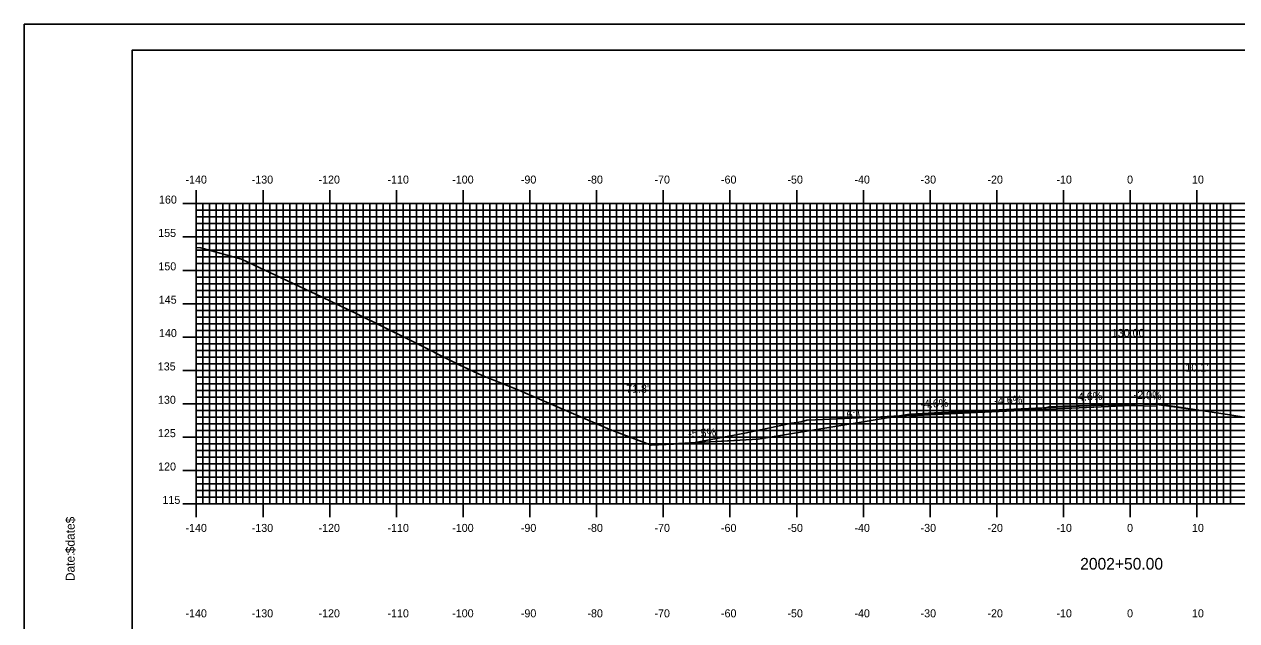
# Model space of a CAD drawing. Extents: x 851139 to 851482, y 366605 to 366825.
# Drawn here: x 851139.2 to 851320.9, y 366735.5 to 366824.9 of the extents above; entities that cross this region are included whole.
import ezdxf

# ---------------------------------------------------------------- set-up
doc = ezdxf.new("R2010")
doc.units = 0
for name, color, linetype in [('ANNOTATION', 7, 'Continuous'), ('BORDER', 7, 'Continuous'), ('D_Roadway_Centerline', 7, 'Continuous'), ('D_Roadway_Centerline_Text', 7, 'Continuous'), ('D_Roadway_Edge_Shoulder', 7, 'Continuous'), ('D_Roadway_Edge_TW', 7, 'Continuous'), ('D_Roadway_SlopeLines', 7, 'Continuous'), ('D_Text_Standard', 7, 'Continuous'), ('H_V ANNOTATION', 7, 'Continuous'), ('M_Roadway_Centerline', 7, 'Continuous'), ('MAJOR', 7, 'Continuous'), ('MINOR', 7, 'Continuous'), ('PLOT BOUNDARY', 7, 'Continuous'), ('S_Roadway_Centerline', 7, 'Continuous')]:
    doc.layers.add(name, color=color, linetype=linetype)

msp = doc.modelspace()

# ---------------------------------------------------------------- linework, layer by layer
at = {"layer": 'BORDER'}
msp.add_lwpolyline([(851155.34, 366611.06), (851475.34, 366611.06), (851475.34, 366821.06), (851155.34, 366821.06)], close=True, dxfattribs=at)
at = {"layer": 'D_Roadway_Centerline'}
msp.add_line((851304.94, 366768.05), (851308.94, 366767.97), dxfattribs=at)
msp.add_lwpolyline([(851233.14, 366761.87), (851236.34, 366762.05), (851249.16, 366762.75), (851249.16, 366762.75), (851271.86, 366766.53), (851271.86, 366766.53), (851275.61, 366766.7), (851279.85, 366766.9), (851279.86, 366766.9), (851280.94, 366766.95), (851292.94, 366767.5), (851292.94, 366767.5), (851304.94, 366768.05), (851304.94, 366768.05), (851308.94, 366767.97)], dxfattribs=at)
at = {"layer": 'D_Roadway_Edge_Shoulder'}
for points in [[(851304.94, 366768.05), (851308.94, 366767.97), (851308.94, 366767.72), (851304.94, 366767.8)], [(851279.86, 366766.9), (851271.86, 366766.53), (851271.86, 366766.28), (851279.86, 366766.65)]]:
    msp.add_lwpolyline(points, close=True, dxfattribs=at)
at = {"layer": 'D_Roadway_Edge_TW'}
for points in [[(851280.94, 366766.95), (851279.86, 366766.9), (851279.86, 366766.65), (851280.94, 366766.7)], [(851292.94, 366767.5), (851280.94, 366766.95), (851280.94, 366766.7), (851292.94, 366767.25)], [(851304.94, 366768.05), (851292.94, 366767.5), (851292.94, 366767.25), (851304.94, 366767.8)]]:
    msp.add_lwpolyline(points, close=True, dxfattribs=at)
msp.add_lwpolyline([(851280.94, 366766.7), (851280.94, 366766.95)], dxfattribs=at)
at = {"layer": 'D_Roadway_SlopeLines'}
msp.add_line((851308.94, 366767.97), (851315.07, 366767.13), dxfattribs=at)
for points in [[(851271.86, 366766.53), (851249.16, 366762.75)], [(851249.16, 366762.75), (851233.14, 366761.87)]]:
    msp.add_lwpolyline(points, dxfattribs=at)
at = {"layer": 'MAJOR'}
for p, q in [((851164.94, 366800.06), (851164.94, 366798.06)), ((851174.94, 366800.06), (851174.94, 366798.06)), ((851184.94, 366800.06), (851184.94, 366798.06)), ((851194.94, 366800.06), (851194.94, 366798.06)), ((851204.94, 366800.06), (851204.94, 366798.06)), ((851214.94, 366800.06), (851214.94, 366798.06)), ((851224.94, 366800.06), (851224.94, 366798.06)), ((851234.94, 366800.06), (851234.94, 366798.06)), ((851244.94, 366800.06), (851244.94, 366798.06)), ((851254.94, 366800.06), (851254.94, 366798.06)), ((851264.94, 366800.06), (851264.94, 366798.06)), ((851274.94, 366800.06), (851274.94, 366798.06)), ((851284.94, 366800.06), (851284.94, 366798.06)), ((851294.94, 366800.06), (851294.94, 366798.06)), ((851304.94, 366800.06), (851304.94, 366798.06)), ((851314.94, 366800.06), (851314.94, 366798.06)), ((851162.93, 366798.06), (851164.94, 366798.06)), ((851164.94, 366798.06), (851444.94, 366798.06)), ((851164.94, 366753.06), (851164.94, 366798.06)), ((851164.94, 366753.06), (851164.94, 366798.06)), ((851164.94, 366798.06), (851444.94, 366798.06)), ((851174.94, 366753.06), (851174.94, 366798.06)), ((851184.94, 366753.06), (851184.94, 366798.06)), ((851194.94, 366753.06), (851194.94, 366798.06)), ((851204.94, 366753.06), (851204.94, 366798.06)), ((851214.94, 366753.06), (851214.94, 366798.06)), ((851224.94, 366753.06), (851224.94, 366798.06)), ((851234.94, 366753.06), (851234.94, 366798.06)), ((851244.94, 366753.06), (851244.94, 366798.06)), ((851254.94, 366753.06), (851254.94, 366798.06)), ((851264.94, 366753.06), (851264.94, 366798.06)), ((851274.94, 366753.06), (851274.94, 366798.06)), ((851284.94, 366753.06), (851284.94, 366798.06)), ((851294.94, 366753.06), (851294.94, 366798.06)), ((851304.94, 366753.06), (851304.94, 366798.06)), ((851314.94, 366753.06), (851314.94, 366798.06)), ((851162.93, 366793.06), (851164.94, 366793.06)), ((851164.94, 366793.06), (851444.94, 366793.06)), ((851162.93, 366788.06), (851164.94, 366788.06)), ((851164.94, 366788.06), (851444.94, 366788.06)), ((851162.93, 366783.06), (851164.94, 366783.06)), ((851164.94, 366783.06), (851444.94, 366783.06)), ((851162.93, 366778.06), (851164.94, 366778.06)), ((851164.94, 366778.06), (851444.94, 366778.06)), ((851162.93, 366773.06), (851164.94, 366773.06)), ((851164.94, 366773.06), (851444.94, 366773.06)), ((851162.93, 366768.06), (851164.94, 366768.06)), ((851164.94, 366768.06), (851444.94, 366768.06)), ((851162.93, 366763.06), (851164.94, 366763.06)), ((851164.94, 366763.06), (851444.94, 366763.06)), ((851162.93, 366758.06), (851164.94, 366758.06)), ((851164.94, 366758.06), (851444.94, 366758.06)), ((851162.93, 366753.06), (851164.94, 366753.06)), ((851164.94, 366753.06), (851444.94, 366753.06)), ((851164.94, 366753.06), (851444.94, 366753.06)), ((851164.94, 366751.05), (851164.94, 366753.06)), ((851174.94, 366751.05), (851174.94, 366753.06)), ((851184.94, 366751.05), (851184.94, 366753.06)), ((851194.94, 366751.05), (851194.94, 366753.06)), ((851204.94, 366751.05), (851204.94, 366753.06)), ((851214.94, 366751.05), (851214.94, 366753.06)), ((851224.94, 366751.05), (851224.94, 366753.06)), ((851234.94, 366751.05), (851234.94, 366753.06)), ((851244.94, 366751.05), (851244.94, 366753.06)), ((851254.94, 366751.05), (851254.94, 366753.06)), ((851264.94, 366751.05), (851264.94, 366753.06)), ((851274.94, 366751.05), (851274.94, 366753.06)), ((851284.94, 366751.05), (851284.94, 366753.06)), ((851294.94, 366751.05), (851294.94, 366753.06)), ((851304.94, 366751.05), (851304.94, 366753.06)), ((851314.94, 366751.05), (851314.94, 366753.06))]:
    msp.add_line(p, q, dxfattribs=at)
at = {"layer": 'MINOR'}
for p, q in [((851165.94, 366753.06), (851165.94, 366798.06)), ((851166.94, 366753.06), (851166.94, 366798.06)), ((851167.94, 366753.06), (851167.94, 366798.06)), ((851168.94, 366753.06), (851168.94, 366798.06)), ((851169.94, 366753.06), (851169.94, 366798.06)), ((851170.94, 366753.06), (851170.94, 366798.06)), ((851171.94, 366753.06), (851171.94, 366798.06)), ((851172.94, 366753.06), (851172.94, 366798.06)), ((851173.94, 366753.06), (851173.94, 366798.06)), ((851175.94, 366753.06), (851175.94, 366798.06)), ((851176.94, 366753.06), (851176.94, 366798.06)), ((851177.94, 366753.06), (851177.94, 366798.06)), ((851178.94, 366753.06), (851178.94, 366798.06)), ((851179.94, 366753.06), (851179.94, 366798.06)), ((851180.94, 366753.06), (851180.94, 366798.06)), ((851181.94, 366753.06), (851181.94, 366798.06)), ((851182.94, 366753.06), (851182.94, 366798.06)), ((851183.94, 366753.06), (851183.94, 366798.06)), ((851185.94, 366753.06), (851185.94, 366798.06)), ((851186.94, 366753.06), (851186.94, 366798.06)), ((851187.94, 366753.06), (851187.94, 366798.06)), ((851188.94, 366753.06), (851188.94, 366798.06)), ((851189.94, 366753.06), (851189.94, 366798.06)), ((851190.94, 366753.06), (851190.94, 366798.06)), ((851191.94, 366753.06), (851191.94, 366798.06)), ((851192.94, 366753.06), (851192.94, 366798.06)), ((851193.94, 366753.06), (851193.94, 366798.06)), ((851195.94, 366753.06), (851195.94, 366798.06)), ((851196.94, 366753.06), (851196.94, 366798.06)), ((851197.94, 366753.06), (851197.94, 366798.06)), ((851198.94, 366753.06), (851198.94, 366798.06)), ((851199.94, 366753.06), (851199.94, 366798.06)), ((851200.94, 366753.06), (851200.94, 366798.06)), ((851201.94, 366753.06), (851201.94, 366798.06)), ((851202.94, 366753.06), (851202.94, 366798.06)), ((851203.94, 366753.06), (851203.94, 366798.06)), ((851205.94, 366753.06), (851205.94, 366798.06)), ((851206.94, 366753.06), (851206.94, 366798.06)), ((851207.94, 366753.06), (851207.94, 366798.06)), ((851208.94, 366753.06), (851208.94, 366798.06)), ((851209.94, 366753.06), (851209.94, 366798.06)), ((851210.94, 366753.06), (851210.94, 366798.06)), ((851211.94, 366753.06), (851211.94, 366798.06)), ((851212.94, 366753.06), (851212.94, 366798.06)), ((851213.94, 366753.06), (851213.94, 366798.06)), ((851215.94, 366753.06), (851215.94, 366798.06)), ((851216.94, 366753.06), (851216.94, 366798.06)), ((851217.94, 366753.06), (851217.94, 366798.06)), ((851218.94, 366753.06), (851218.94, 366798.06)), ((851219.94, 366753.06), (851219.94, 366798.06)), ((851220.94, 366753.06), (851220.94, 366798.06)), ((851221.94, 366753.06), (851221.94, 366798.06)), ((851222.94, 366753.06), (851222.94, 366798.06)), ((851223.94, 366753.06), (851223.94, 366798.06)), ((851225.94, 366753.06), (851225.94, 366798.06)), ((851226.94, 366753.06), (851226.94, 366798.06)), ((851227.94, 366753.06), (851227.94, 366798.06)), ((851228.94, 366753.06), (851228.94, 366798.06)), ((851229.94, 366753.06), (851229.94, 366798.06)), ((851230.94, 366753.06), (851230.94, 366798.06)), ((851231.94, 366753.06), (851231.94, 366798.06)), ((851232.94, 366753.06), (851232.94, 366798.06)), ((851233.94, 366753.06), (851233.94, 366798.06)), ((851235.94, 366753.06), (851235.94, 366798.06)), ((851236.94, 366753.06), (851236.94, 366798.06)), ((851237.94, 366753.06), (851237.94, 366798.06)), ((851238.94, 366753.06), (851238.94, 366798.06)), ((851239.94, 366753.06), (851239.94, 366798.06)), ((851240.94, 366753.06), (851240.94, 366798.06)), ((851241.94, 366753.06), (851241.94, 366798.06)), ((851242.94, 366753.06), (851242.94, 366798.06)), ((851243.94, 366753.06), (851243.94, 366798.06)), ((851245.94, 366753.06), (851245.94, 366798.06)), ((851246.94, 366753.06), (851246.94, 366798.06)), ((851247.94, 366753.06), (851247.94, 366798.06)), ((851248.94, 366753.06), (851248.94, 366798.06)), ((851249.94, 366753.06), (851249.94, 366798.06)), ((851250.94, 366753.06), (851250.94, 366798.06)), ((851251.94, 366753.06), (851251.94, 366798.06)), ((851252.94, 366753.06), (851252.94, 366798.06)), ((851253.94, 366753.06), (851253.94, 366798.06)), ((851255.94, 366753.06), (851255.94, 366798.06)), ((851256.94, 366753.06), (851256.94, 366798.06)), ((851257.94, 366753.06), (851257.94, 366798.06)), ((851258.94, 366753.06), (851258.94, 366798.06)), ((851259.94, 366753.06), (851259.94, 366798.06)), ((851260.94, 366753.06), (851260.94, 366798.06)), ((851261.94, 366753.06), (851261.94, 366798.06)), ((851262.94, 366753.06), (851262.94, 366798.06)), ((851263.94, 366753.06), (851263.94, 366798.06)), ((851265.94, 366753.06), (851265.94, 366798.06)), ((851266.94, 366753.06), (851266.94, 366798.06)), ((851267.94, 366753.06), (851267.94, 366798.06)), ((851268.94, 366753.06), (851268.94, 366798.06)), ((851269.94, 366753.06), (851269.94, 366798.06)), ((851270.94, 366753.06), (851270.94, 366798.06)), ((851271.94, 366753.06), (851271.94, 366798.06)), ((851272.94, 366753.06), (851272.94, 366798.06)), ((851273.94, 366753.06), (851273.94, 366798.06)), ((851275.94, 366753.06), (851275.94, 366798.06)), ((851276.94, 366753.06), (851276.94, 366798.06)), ((851277.94, 366753.06), (851277.94, 366798.06)), ((851278.94, 366753.06), (851278.94, 366798.06)), ((851279.94, 366753.06), (851279.94, 366798.06)), ((851280.94, 366753.06), (851280.94, 366798.06)), ((851281.94, 366753.06), (851281.94, 366798.06)), ((851282.94, 366753.06), (851282.94, 366798.06)), ((851283.94, 366753.06), (851283.94, 366798.06)), ((851285.94, 366753.06), (851285.94, 366798.06)), ((851286.94, 366753.06), (851286.94, 366798.06)), ((851287.94, 366753.06), (851287.94, 366798.06)), ((851288.94, 366753.06), (851288.94, 366798.06)), ((851289.94, 366753.06), (851289.94, 366798.06)), ((851290.94, 366753.06), (851290.94, 366798.06)), ((851291.94, 366753.06), (851291.94, 366798.06)), ((851292.94, 366753.06), (851292.94, 366798.06)), ((851293.94, 366753.06), (851293.94, 366798.06)), ((851295.94, 366753.06), (851295.94, 366798.06)), ((851296.94, 366753.06), (851296.94, 366798.06)), ((851297.94, 366753.06), (851297.94, 366798.06)), ((851298.94, 366753.06), (851298.94, 366798.06)), ((851299.94, 366753.06), (851299.94, 366798.06)), ((851300.94, 366753.06), (851300.94, 366798.06)), ((851301.94, 366753.06), (851301.94, 366798.06)), ((851302.94, 366753.06), (851302.94, 366798.06)), ((851303.94, 366753.06), (851303.94, 366798.06)), ((851305.94, 366753.06), (851305.94, 366798.06)), ((851306.94, 366753.06), (851306.94, 366798.06)), ((851307.94, 366753.06), (851307.94, 366798.06)), ((851308.94, 366753.06), (851308.94, 366798.06)), ((851309.94, 366753.06), (851309.94, 366798.06)), ((851310.94, 366753.06), (851310.94, 366798.06)), ((851311.94, 366753.06), (851311.94, 366798.06)), ((851312.94, 366753.06), (851312.94, 366798.06)), ((851313.94, 366753.06), (851313.94, 366798.06)), ((851315.94, 366753.06), (851315.94, 366798.06)), ((851316.94, 366753.06), (851316.94, 366798.06)), ((851317.94, 366753.06), (851317.94, 366798.06)), ((851318.94, 366753.06), (851318.94, 366798.06)), ((851319.94, 366753.06), (851319.94, 366798.06)), ((851164.94, 366797.06), (851444.94, 366797.06)), ((851164.94, 366797.06), (851166.94, 366797.06)), ((851164.94, 366796.06), (851444.94, 366796.06)), ((851164.94, 366796.06), (851166.94, 366796.06)), ((851164.94, 366795.06), (851444.94, 366795.06)), ((851164.94, 366795.06), (851166.94, 366795.06)), ((851164.94, 366794.06), (851444.94, 366794.06)), ((851164.94, 366794.06), (851166.94, 366794.06)), ((851164.94, 366792.06), (851444.94, 366792.06)), ((851164.94, 366792.06), (851166.94, 366792.06)), ((851164.94, 366791.06), (851444.94, 366791.06)), ((851164.94, 366791.06), (851166.94, 366791.06)), ((851164.94, 366790.06), (851444.94, 366790.06)), ((851164.94, 366790.06), (851166.94, 366790.06)), ((851164.94, 366789.06), (851444.94, 366789.06)), ((851164.94, 366789.06), (851166.94, 366789.06)), ((851164.94, 366787.06), (851444.94, 366787.06)), ((851164.94, 366787.06), (851166.94, 366787.06)), ((851164.94, 366786.06), (851444.94, 366786.06)), ((851164.94, 366786.06), (851166.94, 366786.06)), ((851164.94, 366785.06), (851444.94, 366785.06)), ((851164.94, 366785.06), (851166.94, 366785.06)), ((851164.94, 366784.06), (851444.94, 366784.06)), ((851164.94, 366784.06), (851166.94, 366784.06)), ((851164.94, 366782.06), (851444.94, 366782.06)), ((851164.94, 366782.06), (851166.94, 366782.06)), ((851164.94, 366781.06), (851444.94, 366781.06)), ((851164.94, 366781.06), (851166.94, 366781.06)), ((851164.94, 366780.06), (851444.94, 366780.06)), ((851164.94, 366780.06), (851166.94, 366780.06)), ((851164.94, 366779.06), (851444.94, 366779.06)), ((851164.94, 366779.06), (851166.94, 366779.06)), ((851164.94, 366777.06), (851444.94, 366777.06)), ((851164.94, 366777.06), (851166.94, 366777.06)), ((851164.94, 366776.06), (851444.94, 366776.06)), ((851164.94, 366776.06), (851166.94, 366776.06)), ((851164.94, 366775.06), (851444.94, 366775.06)), ((851164.94, 366775.06), (851166.94, 366775.06)), ((851164.94, 366774.06), (851444.94, 366774.06)), ((851164.94, 366774.06), (851166.94, 366774.06)), ((851164.94, 366772.06), (851444.94, 366772.06)), ((851164.94, 366772.06), (851166.94, 366772.06)), ((851164.94, 366771.06), (851444.94, 366771.06)), ((851164.94, 366771.06), (851166.94, 366771.06)), ((851164.94, 366770.06), (851444.94, 366770.06)), ((851164.94, 366770.06), (851166.94, 366770.06)), ((851164.94, 366769.06), (851444.94, 366769.06)), ((851164.94, 366769.06), (851166.94, 366769.06)), ((851164.94, 366767.06), (851444.94, 366767.06)), ((851164.94, 366767.06), (851166.94, 366767.06)), ((851164.94, 366766.06), (851444.94, 366766.06)), ((851164.94, 366766.06), (851166.94, 366766.06)), ((851164.94, 366765.06), (851444.94, 366765.06)), ((851164.94, 366765.06), (851166.94, 366765.06)), ((851164.94, 366764.06), (851444.94, 366764.06)), ((851164.94, 366764.06), (851166.94, 366764.06)), ((851164.94, 366762.06), (851444.94, 366762.06)), ((851164.94, 366762.06), (851166.94, 366762.06)), ((851164.94, 366761.06), (851444.94, 366761.06)), ((851164.94, 366761.06), (851166.94, 366761.06)), ((851164.94, 366760.06), (851444.94, 366760.06)), ((851164.94, 366760.06), (851166.94, 366760.06)), ((851164.94, 366759.06), (851444.94, 366759.06)), ((851164.94, 366759.06), (851166.94, 366759.06)), ((851164.94, 366757.06), (851444.94, 366757.06)), ((851164.94, 366757.06), (851166.94, 366757.06)), ((851164.94, 366756.06), (851444.94, 366756.06)), ((851164.94, 366756.06), (851166.94, 366756.06)), ((851164.94, 366755.06), (851444.94, 366755.06)), ((851164.94, 366755.06), (851166.94, 366755.06)), ((851164.94, 366754.06), (851444.94, 366754.06)), ((851164.94, 366754.06), (851166.94, 366754.06))]:
    msp.add_line(p, q, dxfattribs=at)
at = {"layer": 'PLOT BOUNDARY'}
msp.add_lwpolyline([(851139.15, 366604.94), (851479.15, 366604.94), (851479.15, 366824.94), (851139.15, 366824.94)], close=True, dxfattribs=at)
at = {"layer": 'S_Roadway_Centerline'}
msp.add_lwpolyline([(851164.94, 366791.49), (851165.61, 366791.44), (851171.73, 366789.75), (851183.83, 366784.05), (851189.12, 366781.48), (851196.79, 366777.69), (851204.34, 366773.9), (851207.8, 366772.31), (851213.03, 366770.22), (851226.94, 366764.22), (851233.14, 366761.87), (851238.72, 366762.09), (851238.91, 366762.09), (851247.16, 366763.67), (851254.19, 366765.18), (851255.59, 366765.38), (851256.48, 366765.62), (851257.74, 366765.68), (851267.57, 366766.13), (851274.3, 366766.47), (851288.27, 366767.21), (851291.68, 366767.4), (851292.3, 366767.44), (851292.8, 366767.6), (851295.08, 366767.68), (851303, 366767.92), (851307.08, 366768.05), (851308.73, 366768.1), (851309.96, 366767.91), (851320.18, 366766.34), (851327.58, 366765.17)], dxfattribs=at)

# ---------------------------------------------------------------- texts
at = {"layer": 'ANNOTATION'}
for s, rotation, p in [('-4.6%', 2.6338, (851273.5, 366767.41)), ('-4.6%', 2.6338, (851284.58, 366767.92)), ('-4.6%', 2.6335, (851296.58, 366768.47)), ('-2.0%', 357.7089, (851305.42, 366768.83)), ('6:1', 9.4613, (851262.53, 366765.75)), ('-5.5%', 3.1231, (851238.69, 366762.98))]:
    msp.add_text(s, height=1.2, rotation=rotation, dxfattribs=at).set_placement(p)
at = {"layer": 'BORDER'}
for s, p in [('$date$', (851146.71, 366745.67)), ('Date:', (851146.71, 366741.49))]:
    msp.add_text(s, height=1.339, rotation=90, dxfattribs=at).set_placement(p)
at = {"layer": 'D_Roadway_Centerline_Text'}
msp.add_text('130.00', height=1.2, dxfattribs=at).set_placement((851302.17, 366778.08))
at = {"layer": 'D_Text_Standard'}
for s, p in [("10.1'", (851313.21, 366772.89)), ("71.8'", (851229.37, 366769.71))]:
    msp.add_text(s, height=1.2, dxfattribs=at).set_placement(p)
at = {"layer": 'H_V ANNOTATION'}
for s, height, p in [('-140', 1.2, (851163.32, 366801.06)), ('-130', 1.2, (851173.25, 366801.06)), ('-120', 1.2, (851183.26, 366801.06)), ('-110', 1.2, (851193.6, 366801.06)), ('-100', 1.2, (851203.3, 366801.06)), ('-90', 1.2, (851213.59, 366801.06)), ('-80', 1.2, (851223.57, 366801.06)), ('-70', 1.2, (851233.62, 366801.06)), ('-60', 1.2, (851243.59, 366801.06)), ('-50', 1.2, (851253.55, 366801.06)), ('-40', 1.2, (851263.59, 366801.06)), ('-30', 1.2, (851273.51, 366801.06)), ('-20', 1.2, (851283.53, 366801.06)), ('-10', 1.2, (851293.87, 366801.06)), ('0', 1.2, (851304.46, 366801.06)), ('10', 1.2, (851314.19, 366801.06)), ('160', 1.2, (851159.35, 366798.06)), ('155', 1.2, (851159.23, 366793.06)), ('150', 1.2, (851159.26, 366788.06)), ('145', 1.2, (851159.32, 366783.06)), ('140', 1.2, (851159.35, 366778.06)), ('135', 1.2, (851159.17, 366773.06)), ('130', 1.2, (851159.2, 366768.06)), ('125', 1.2, (851159.19, 366763.06)), ('120', 1.2, (851159.22, 366758.06)), ('115', 1.2, (851159.87, 366753.06)), ('-140', 1.2, (851163.32, 366748.86)), ('-130', 1.2, (851173.25, 366748.86)), ('-120', 1.2, (851183.26, 366748.86)), ('-110', 1.2, (851193.6, 366748.86)), ('-100', 1.2, (851203.3, 366748.86)), ('-90', 1.2, (851213.59, 366748.86)), ('-80', 1.2, (851223.57, 366748.86)), ('-70', 1.2, (851233.62, 366748.86)), ('-60', 1.2, (851243.59, 366748.86)), ('-50', 1.2, (851253.55, 366748.86)), ('-40', 1.2, (851263.59, 366748.86)), ('-30', 1.2, (851273.51, 366748.86)), ('-20', 1.2, (851283.53, 366748.86)), ('-10', 1.2, (851293.87, 366748.86)), ('0', 1.2, (851304.46, 366748.86)), ('10', 1.2, (851314.19, 366748.86)), ('2002+50.00', 1.75, (851297.43, 366743.21)), ('-140', 1.2, (851163.32, 366736.06)), ('-130', 1.2, (851173.25, 366736.06)), ('-120', 1.2, (851183.26, 366736.06)), ('-110', 1.2, (851193.6, 366736.06)), ('-100', 1.2, (851203.3, 366736.06)), ('-90', 1.2, (851213.59, 366736.06)), ('-80', 1.2, (851223.57, 366736.06)), ('-70', 1.2, (851233.62, 366736.06)), ('-60', 1.2, (851243.59, 366736.06)), ('-50', 1.2, (851253.55, 366736.06)), ('-40', 1.2, (851263.59, 366736.06)), ('-30', 1.2, (851273.51, 366736.06)), ('-20', 1.2, (851283.53, 366736.06)), ('-10', 1.2, (851293.87, 366736.06)), ('0', 1.2, (851304.46, 366736.06)), ('10', 1.2, (851314.19, 366736.06))]:
    msp.add_text(s, height=height, dxfattribs=at).set_placement(p)
at = {"layer": 'M_Roadway_Centerline'}
for s, p in [('C', (851292.8, 366767.6)), ('L', (851292.8, 366767.59))]:
    msp.add_text(s, height=0.0146, dxfattribs=at).set_placement(p)
at = {"layer": 'MAJOR'}
msp.add_text('-', height=0.012, dxfattribs=at).set_placement((851164.93, 366753.06))

doc.saveas('drawing.dxf')
